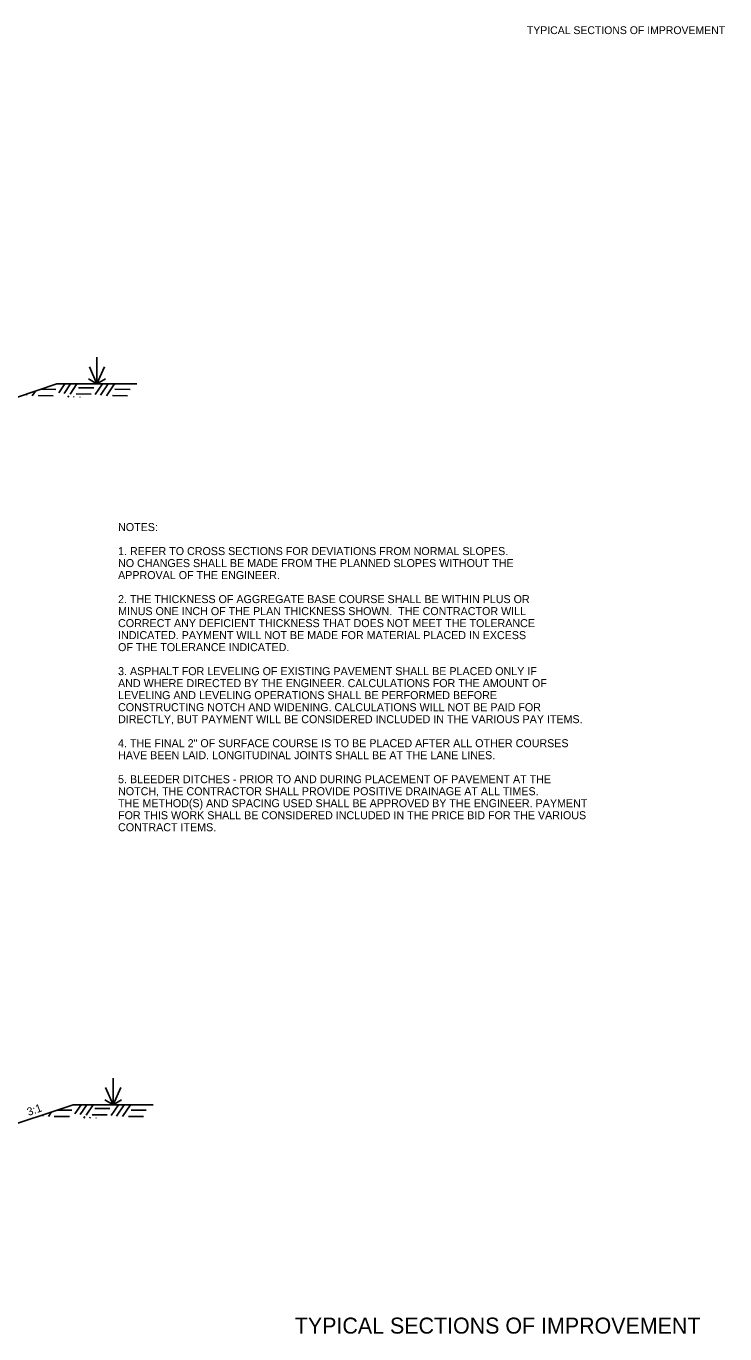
# Model space of a CAD drawing. Extents: x -900 to 15312, y 1857 to 2945.
# Drawn here: x 2476 to 3000, y 1965 to 2945 of the extents above; entities that cross this region are included whole.
import ezdxf

# ---------------------------------------------------------------- set-up
doc = ezdxf.new("R2010")
doc.units = 0
for name, color, linetype in [('R_Annotation', 7, 'Continuous'), ('R_Border', 7, 'Continuous'), ('R_Dimension', 7, 'Continuous'), ('R_Draft', 7, 'Continuous')]:
    doc.layers.add(name, color=color, linetype=linetype)

msp = doc.modelspace()

# ---------------------------------------------------------------- linework, layer by layer
at = {"layer": 'R_Annotation'}
for p, q in [((2439.09, 2656.72), (2499.09, 2676.72)), ((2499.09, 2676.72), (2559.09, 2676.72)), ((2451.18, 2116.41), (2511.18, 2136.41)), ((2511.18, 2136.41), (2571.18, 2136.41))]:
    msp.add_line(p, q, dxfattribs=at)
at = {"layer": 'R_Dimension'}
for p, q in [((2500.5, 2669.98), (2505.05, 2676.72)), ((2504.48, 2669.51), (2509.35, 2676.72)), ((2508.93, 2669.05), (2514.11, 2676.72)), ((2527.75, 2668.77), (2533.12, 2676.72)), ((2531.74, 2668.31), (2537.42, 2676.72)), ((2536.19, 2667.84), (2542.18, 2676.72)), ((2476.12, 2668.31), (2476.78, 2669.29)), ((2480.57, 2667.84), (2482.93, 2671.34)), ((2485.02, 2668.03), (2496.33, 2667.94)), ((2487.18, 2672.76), (2498.27, 2672.67)), ((2507.25, 2666.72), (2508.01, 2667.84)), ((2511.55, 2666.72), (2511.99, 2667.38)), ((2513.38, 2669.23), (2524.69, 2669.14)), ((2515.33, 2673.96), (2526.64, 2673.87)), ((2516.31, 2666.72), (2516.44, 2666.92)), ((2540.64, 2668.03), (2551.95, 2667.94)), ((2542.58, 2672.76), (2553.89, 2672.67)), ((2488.21, 2127.99), (2488.87, 2128.98)), ((2492.66, 2127.53), (2495.02, 2131.02)), ((2497.11, 2127.71), (2508.42, 2127.62)), ((2499.27, 2132.44), (2510.37, 2132.35)), ((2512.59, 2129.66), (2517.14, 2136.41)), ((2516.58, 2129.2), (2521.44, 2136.41)), ((2519.35, 2126.41), (2520.1, 2127.53)), ((2521.03, 2128.73), (2526.21, 2136.41)), ((2525.48, 2128.92), (2536.79, 2128.83)), ((2527.42, 2133.65), (2538.73, 2133.56)), ((2539.85, 2128.46), (2545.21, 2136.41)), ((2543.83, 2127.99), (2549.51, 2136.41)), ((2548.28, 2127.53), (2554.27, 2136.41)), ((2552.73, 2127.71), (2564.04, 2127.62)), ((2554.68, 2132.44), (2565.99, 2132.35)), ((2523.65, 2126.41), (2524.09, 2127.07)), ((2528.41, 2126.41), (2528.54, 2126.6))]:
    msp.add_line(p, q, dxfattribs=at)
at = {"layer": 'R_Draft'}
for p, q in [((2529.09, 2676.72), (2529.09, 2696.81)), ((2529.09, 2676.72), (2523.39, 2689.65)), ((2529.09, 2676.72), (2534.78, 2689.65)), ((2529.09, 2676.72), (2522.79, 2680.51)), ((2529.09, 2676.72), (2535.38, 2680.51)), ((2541.18, 2136.41), (2541.18, 2156.5)), ((2541.18, 2136.41), (2535.49, 2149.34)), ((2541.18, 2136.41), (2546.87, 2149.34)), ((2541.18, 2136.41), (2534.89, 2140.2)), ((2541.18, 2136.41), (2547.47, 2140.2))]:
    msp.add_line(p, q, dxfattribs=at)

# ---------------------------------------------------------------- texts
at = {"layer": 'R_Annotation'}
for s, height, p in [('NOTES:', 6, (2544.9, 2566.47)), ('1. REFER TO CROSS SECTIONS FOR DEVIATIONS FROM NORMAL SLOPES. ', 6, (2544.9, 2548.47)), ('NO CHANGES SHALL BE MADE FROM THE PLANNED SLOPES WITHOUT THE', 6, (2544.9, 2539.47)), ('APPROVAL OF THE ENGINEER.', 6, (2544.9, 2530.47)), ('2. THE THICKNESS OF AGGREGATE BASE COURSE SHALL BE WITHIN PLUS OR', 6, (2544.9, 2512.47)), ('MINUS ONE INCH OF THE PLAN THICKNESS SHOWN.  THE CONTRACTOR WILL', 6, (2544.9, 2503.47)), ('CORRECT ANY DEFICIENT THICKNESS THAT DOES NOT MEET THE TOLERANCE', 6, (2544.9, 2494.47)), ('INDICATED. PAYMENT WILL NOT BE MADE FOR MATERIAL PLACED IN EXCESS', 6, (2544.9, 2485.47)), ('OF THE TOLERANCE INDICATED.', 6, (2544.9, 2476.47)), ('3. ASPHALT FOR LEVELING OF EXISTING PAVEMENT SHALL BE PLACED ONLY IF', 6, (2544.9, 2458.47)), ('AND WHERE DIRECTED BY THE ENGINEER. CALCULATIONS FOR THE AMOUNT OF ', 6, (2544.9, 2449.47)), ('LEVELING AND LEVELING OPERATIONS SHALL BE PERFORMED BEFORE', 6, (2544.9, 2440.47)), ('CONSTRUCTING NOTCH AND WIDENING. CALCULATIONS WILL NOT BE PAID FOR', 6, (2544.9, 2431.47)), ('DIRECTLY, BUT PAYMENT WILL BE CONSIDERED INCLUDED IN THE VARIOUS PAY ITEMS.', 6, (2544.9, 2422.47)), ('4. THE FINAL 2" OF SURFACE COURSE IS TO BE PLACED AFTER ALL OTHER COURSES', 6, (2544.9, 2404.47)), ('HAVE BEEN LAID. LONGITUDINAL JOINTS SHALL BE AT THE LANE LINES.', 6, (2544.9, 2395.47)), ('5. BLEEDER DITCHES - PRIOR TO AND DURING PLACEMENT OF PAVEMENT AT THE ', 6, (2544.9, 2377.47)), ('NOTCH, THE CONTRACTOR SHALL PROVIDE POSITIVE DRAINAGE AT ALL TIMES. ', 6, (2544.9, 2368.47)), ('THE METHOD(S) AND SPACING USED SHALL BE APPROVED BY THE ENGINEER. PAYMENT', 6, (2544.9, 2359.47)), ('FOR THIS WORK SHALL BE CONSIDERED INCLUDED IN THE PRICE BID FOR THE VARIOUS', 6, (2544.9, 2350.47)), ('CONTRACT ITEMS.', 6, (2544.9, 2341.47)), ('TYPICAL SECTIONS OF IMPROVEMENT', 12, (2677.38, 1964.9))]:
    msp.add_text(s, height=height, dxfattribs=at).set_placement(p)
msp.add_text('3:1', height=6, rotation=19.33935, dxfattribs=at).set_placement((2477.84, 2128.01))
at = {"layer": 'R_Border'}
msp.add_text('TYPICAL SECTIONS OF IMPROVEMENT', height=5.862, dxfattribs=at).set_placement((2851.36, 2938.99))

doc.saveas('drawing.dxf')
